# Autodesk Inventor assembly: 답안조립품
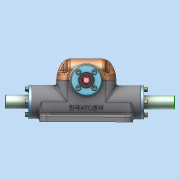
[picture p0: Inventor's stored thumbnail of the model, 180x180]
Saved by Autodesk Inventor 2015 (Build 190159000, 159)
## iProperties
Created: 2024-06
Part Number: 답안조립품
Document SubType Name: Assembly
Designer: Administrator
Author: Administrator
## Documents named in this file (13)
- C:\Users\Administrator\Desktop\740604V1012\답안조립품.iam
- C:\Users\Administrator\Desktop\740604V1012\본체.ipt
- C:\Users\Administrator\Desktop\740604V1012\랙.ipt
- C:\Users\Administrator\Desktop\740604V1012\칼라.ipt
- C:\Users\Administrator\Desktop\740604V1012\피니언.ipt
- C:\Users\Administrator\Desktop\740604V1012\깊은 홈 볼 베어링 6901.ipt
- C:\Users\Administrator\Desktop\740604V1012\윗커버.ipt
- C:\Users\Administrator\Desktop\740604V1012\베어링 커버.ipt
- C:\Users\Administrator\Desktop\740604V1012\오일실 12 22 7.ipt
- C:\Users\Administrator\Desktop\740604V1012\오일레스 부시.ipt
- C:\Users\Administrator\Desktop\740604V1012\부시 커버.ipt
- C:\Users\Administrator\Desktop\740604V1012\스프링 와셔 M4.ipt
- C:\Users\Administrator\Desktop\740604V1012\육각 소켓 머리 볼트 M4x10.ipt
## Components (4 placed, 1 different names)
1. 피니언:1
2. 피니언:2
3. 피니언:3
4. 피니언:4
